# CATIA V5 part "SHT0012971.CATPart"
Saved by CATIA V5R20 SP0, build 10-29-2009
Part number: SHT0012971
Bounding box of the stored display mesh (mm): x 87.772 to 118.529, y -996.401 to -849.286, z 939.253 to 1127.424
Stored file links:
  D:\新建文件夹\宋国明\项目\02-福田A6-张甲\骨架钣金\2D\SHT0012971-安全带上悬置固定板总成\SHT0012971.CATPart

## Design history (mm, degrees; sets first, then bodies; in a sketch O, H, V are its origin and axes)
Set1 "安全带上悬置固定板\\几何图形集.1"
  Point1: stored without definition
Body1 (main body)
Body2 "安全带上悬置固定板\\零件几何体"
  Solid1: solid without history
Body3 "汽车安全带用焊接螺母\\几何体.2"
  Solid2 "实体.1": solid without history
